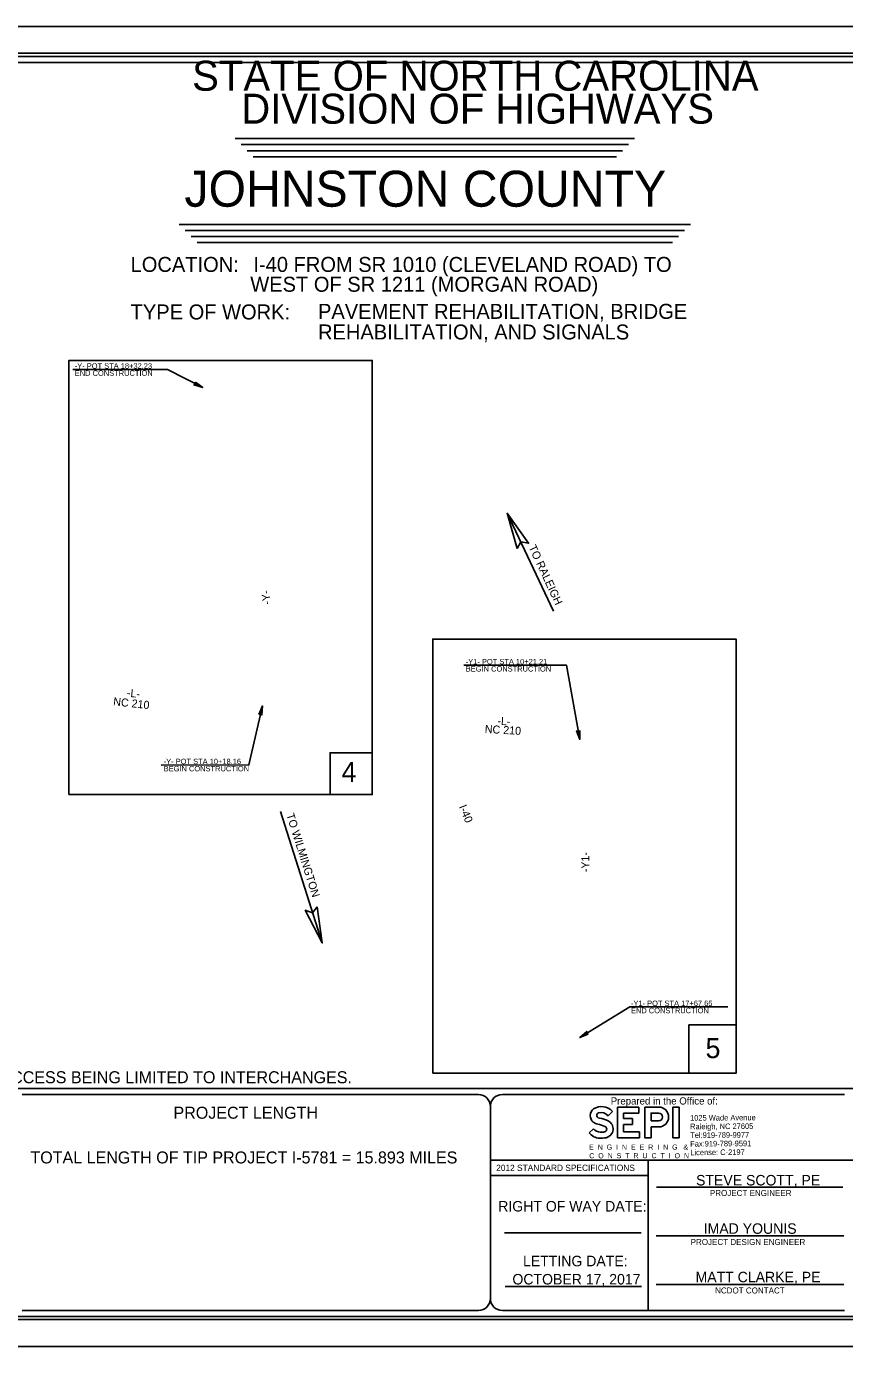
# Model space of a CAD drawing. Extents: x 2128934 to 2134034, y 641595 to 644895.
# Drawn here: x 2130661 to 2132705, y 641595 to 644895 of the extents above; entities that cross this region are included whole.
import ezdxf

# ---------------------------------------------------------------- set-up
doc = ezdxf.new("R2010")
doc.units = 0
for name, color, linetype in [('Old_Level_2', 7, 'Continuous'), ('Old_Level_61', 7, 'Continuous'), ('Prop Dimension Text', 7, 'Continuous'), ('Prop DSN Text', 7, 'Continuous'), ('Prop Terminator CELL', 7, 'Continuous'), ('Sheet Data Field CELL', 7, 'Continuous'), ('Sheet Plot Border Inside CELL', 7, 'Continuous'), ('Sheet Plot Border Outside CELL', 7, 'Continuous'), ('Sheet Title CELL', 7, 'Continuous'), ('Sheet Title Data Points CELL', 7, 'Continuous')]:
    doc.layers.add(name, color=color, linetype=linetype)

msp = doc.modelspace()

# ---------------------------------------------------------------- linework, layer by layer
at = {"layer": 'Old_Level_61'}
for p, q in [((2132124.8, 642183), (2132113.8, 642172.2)), ((2132137.3, 642117.1), (2132137.3, 642193.7)), ((2132137.3, 642193.7), (2132190.5, 642193.7)), ((2132190.5, 642193.7), (2132190.5, 642178.8)), ((2132240.3, 642193.8), (2132205.6, 642193.7)), ((2132276, 642193.8), (2132291.3, 642193.8)), ((2132276, 642117.1), (2132276, 642193.8)), ((2132291.3, 642193.8), (2132291.3, 642117.1)), ((2132190.5, 642178.8), (2132152.6, 642178.8)), ((2132152.6, 642178.8), (2132152.6, 642165.5)), ((2132152.6, 642165.5), (2132174.5, 642165.5)), ((2132174.5, 642150.6), (2132152.6, 642150.6)), ((2132152.6, 642150.6), (2132152.6, 642132)), ((2132174.5, 642165.5), (2132174.5, 642150.6)), ((2132240.3, 642159.1), (2132221.3, 642159.1)), ((2132066.5, 642129.7), (2132077.6, 642139.6)), ((2132192.3, 642117.1), (2132137.3, 642117.1)), ((2132152.6, 642132), (2132192.3, 642132)), ((2132192.3, 642132), (2132192.3, 642117.1)), ((2132291.3, 642117.1), (2132276, 642117.1))]:
    msp.add_line(p, q, dxfattribs=at)
for points in [[(2132205.6, 642193.7), (2132240.3, 642193.8)], [(2132240.3, 642144.2), (2132221.3, 642144.2), (2132221.3, 642117.1), (2132205.6, 642117.1), (2132205.6, 642193.7)], [(2132205.6, 642193.7), (2132205.6, 642117.1), (2132221.3, 642117.1), (2132221.3, 642144.2), (2132240.3, 642144.2)], [(2132221.3, 642159.1), (2132221.3, 642178.9), (2132240.3, 642178.9)], [(2132221.3, 642159.1), (2132221.3, 642178.9), (2132240.3, 642178.9)], [(2132240.3, 642159.1), (2132221.3, 642159.1)]]:
    msp.add_lwpolyline(points, dxfattribs=at)
for centre, radius, start, end in [((2132090.7, 642172.3), 21.3, 127.7369, 229.6652), ((2132097.6, 642158.3), 36.7, 42.1326, 122.978), ((2132096.3, 642156.7), 23.4, 41.6205, 105.1977), ((2132240.3, 642169), 24.8, 270.0084, 90.0084), ((2132240.3, 642169), 24.8, 270.0084, 90.0084), ((2132095.2, 642181.3), 31.1, 234.0274, 257.3507), ((2132091.7, 642173.1), 6.34, 103.5309, 215.5146), ((2132095.1, 642177.9), 12.1, 224.8335, 256.8487), ((2132070.5, 642058.6), 94, 67.7855, 79.0603), ((2132072.8, 642061.8), 106.2, 67.2046, 79.386), ((2132103.9, 642139.3), 22.7, 283.8986, 63.5915), ((2132240.3, 642169), 9.87, 270.0084, 90.0084), ((2132240.3, 642169), 9.87, 270.0084, 90.0084), ((2132093.5, 642149.6), 33.5, 216.3694, 269.0231), ((2132096.1, 642154.7), 23.8, 219.2142, 265.7728), ((2132097.2, 642166.6), 50.7, 265.1338, 283.7744), ((2132097.5, 642160.4), 29.6, 263.8471, 285.0484), ((2132103.1, 642138.9), 7.37, 286.1133, 66.6482)]:
    msp.add_arc(centre, radius, start, end, dxfattribs=at)
at = {"layer": 'Prop Dimension Text'}
for p, q in [((2130776.9, 644037.7), (2131013.2, 644037.8)), ((2131013.2, 644037.8), (2131101.3, 643992.3))]:
    msp.add_line(p, q, dxfattribs=at)
for points in [[(2131753.5, 643298.2), (2132009.9, 643298.5), (2132043.2, 643112.7)], [(2130996.9, 643048.8), (2131216.6, 643048.9), (2131250.2, 643196.6)], [(2132043.2, 642367.5), (2132167.9, 642444.1), (2132412.8, 642444.1)]]:
    msp.add_lwpolyline(points, dxfattribs=at)
at = {"layer": 'Prop DSN Text'}
for p, q in [((2131977.4, 643433.6), (2131862, 643678.1)), ((2131295.6, 642933), (2131399.6, 642604.2))]:
    msp.add_line(p, q, dxfattribs=at)
for points in [[(2130767, 642975), (2130767, 644060.1), (2131524.6, 644060.1), (2131524.6, 642975)], [(2131886.4, 643590.1), (2131862, 643678.1), (2131915.1, 643603.1), (2131895.7, 643606.7)], [(2131675.9, 642278.4), (2131675.9, 643363.5), (2132433.5, 643363.5), (2132433.5, 642278.4)], [(2131524.6, 642975), (2131419.2, 642975), (2131419.2, 643079.5), (2131524.6, 643079.5)], [(2131387.3, 642694.7), (2131399.6, 642604.2), (2131357.1, 642685.7), (2131375.8, 642679.5)], [(2132433.5, 642278.4), (2132315.9, 642278.4), (2132315.9, 642399.3), (2132433.5, 642399.3)]]:
    msp.add_lwpolyline(points, close=True, dxfattribs=at)
at = {"layer": 'Prop Terminator CELL'}
for points in [[(2131083.1, 644006), (2131101.3, 643992.3), (2131079.3, 643999.1), (2131083.7, 644001.3)], [(2131241.4, 643175.5), (2131250.2, 643196.6), (2131249, 643173.7), (2131245.8, 643177.4)], [(2132043, 643135.5), (2132043.2, 643112.7), (2132035.2, 643134.2), (2132039.7, 643132.1)], [(2132064.4, 642376), (2132043.2, 642367.5), (2132060.4, 642382.8), (2132060, 642377.8)]]:
    msp.add_lwpolyline(points, close=True, dxfattribs=at)
at = {"layer": 'Sheet Plot Border Inside CELL'}
msp.add_lwpolyline([(2128972.8, 641662.5), (2133972.3, 641662.5), (2133972.3, 644827.8), (2128972.8, 644827.8)], close=True, dxfattribs=at)
at = {"layer": 'Sheet Plot Border Outside CELL'}
msp.add_lwpolyline([(2128933.8, 641595.1), (2134033.8, 641595.1), (2134033.8, 644895.1), (2128933.8, 644895.1)], close=True, dxfattribs=at)
at = {"layer": 'Sheet Title CELL'}
for p, q in [((2131182, 644614.5), (2132180.2, 644614.5)), ((2131197, 644599.5), (2132165.2, 644599.5)), ((2131212, 644584.5), (2132150.2, 644584.5)), ((2131227, 644569.5), (2132135.2, 644569.5)), ((2131042, 644399.7), (2132320, 644399.7)), ((2131057, 644384.7), (2132305, 644384.7)), ((2131072, 644369.7), (2132290, 644369.7)), ((2131087, 644354.7), (2132275, 644354.7)), ((2129629.8, 642240.2), (2133889.8, 642240.2)), ((2130649.8, 642225.1), (2131789.8, 642225.1)), ((2131849.8, 642225.2), (2132704.8, 642225.2)), ((2131819.8, 642195.2), (2131819.8, 641715.2)), ((2132734.8, 642060.9), (2131819.8, 642060.9)), ((2132214.4, 642060.9), (2132214.4, 641685.2)), ((2132214.4, 642022.6), (2131819.8, 642022.7)), ((2132100.7, 642022.7), (2132100.7, 642022.7)), ((2132235.1, 641994), (2132700.6, 641994)), ((2132196.4, 641879.1), (2131855.2, 641879.1)), ((2132025.7, 641879.1), (2132025.7, 641879.1)), ((2132234.1, 641871.7), (2132702.8, 641871.7)), ((2132197.6, 641745.3), (2131856.4, 641745.3)), ((2132234.1, 641750.6), (2132702.8, 641750.6))]:
    msp.add_line(p, q, dxfattribs=at)
for points in [[(2133904.8, 644820.1), (2129464.7, 644820.2)], [(2133889.8, 644805.1), (2129629.8, 644805.1)], [(2130649.8, 641685.1), (2131789.8, 641685.1)], [(2131849.8, 641685.2), (2132704.8, 641685.1)], [(2129464.8, 641670.1), (2133904.8, 641670.1)]]:
    msp.add_lwpolyline(points, dxfattribs=at)
for centre, start, end in [((2131789.8, 642195.3), 0, 90), ((2131849.8, 642195.3), 90, 180), ((2131789.8, 641715.3), 270, 360), ((2131849.8, 641715.3), 180, 270)]:
    msp.add_arc(centre, 30, start, end, dxfattribs=at)
at = {"layer": 'Sheet Title Data Points CELL'}
for p, q in [((2131685.7, 644444.4), (2131685.7, 644444.4)), ((2132045.8, 644281.3), (2132045.8, 644281.3))]:
    msp.add_line(p, q, dxfattribs=at)

# ---------------------------------------------------------------- texts
at = {"layer": 'Old_Level_2'}
for s, height, rotation, p in [('1025 Wade Avenue', 13.973, 0.3479, (2132318.7, 642159.8)), ('Raleigh, NC 27605', 13.973, 0.3479, (2132318.9, 642138.2)), ('Tel:919-789-9977 ', 13.973, 0.3479, (2132319, 642116.6)), ('E  N  G  I  N  E  E  R  I  N  G   &', 12.75, 0.0085, (2132066.4, 642087.4)), ('Fax:919-789-9591', 13.973, 0.3479, (2132319.1, 642095.1)), ('License: C-2197', 13.973, 0.3479, (2132319.3, 642073.5)), ('C  O  N  S  T  R  U  C  T  I  O  N', 12.75, 0.0085, (2132066.8, 642065.9))]:
    msp.add_text(s, height=height, rotation=rotation, dxfattribs=at).set_placement(p)
at = {"layer": 'Prop Dimension Text'}
for s, p in [('-Y- POT STA 18+32.23', (2130781.4, 644039.6)), ('END CONSTRUCTION', (2130781.5, 644021.6)), ('-Y1- POT STA 10+21.21', (2131758.4, 643300.5)), ('BEGIN CONSTRUCTION', (2131758.4, 643282.5)), ('-Y- POT STA 10+18.16', (2131003.6, 643051)), ('BEGIN CONSTRUCTION', (2131003.6, 643033)), ('-Y1- POT STA 17+67.65', (2132171.1, 642446.4)), ('END CONSTRUCTION', (2132171.1, 642428.4))]:
    msp.add_text(s, height=13.5, rotation=0.0155, dxfattribs=at).set_placement(p)
at = {"layer": 'Prop DSN Text'}
for s, rotation, p in [('TO RALEIGH', 294.9563, (2131914.7, 643593.4)), ('-Y-', 95.3672, (2131270.7, 643450.7)), ('-L-', 353.8891, (2130910.9, 643219.9)), ('NC 210', 353.8891, (2130876.8, 643198.2)), ('NC 210', 356.749, (2131805.4, 643129.2)), ('-L-', 356.749, (2131837, 643149.5)), ('I-40', 292.3368, (2131740.9, 642944.8)), ('TO WILMINGTON', 287.4843, (2131309.7, 642924.6)), ('-Y1-', 89.836, (2132066.8, 642780.8))]:
    msp.add_text(s, height=20, rotation=rotation, dxfattribs=at).set_placement(p)
for s, height, p in [('4', 50, (2131448.1, 643006.8)), ('5', 50, (2132357.4, 642316.2)), ('THIS IS A CONTROLLED-ACCESS PROJECT WITH ACCESS BEING LIMITED TO INTERCHANGES.', 30, (2129630.5, 642253.4)), ('TOTAL LENGTH OF TIP PROJECT I-5781 = 15.893 MILES', 30, (2130670.6, 642052.9))]:
    msp.add_text(s, height=height, dxfattribs=at).set_placement(p)
at = {"layer": 'Sheet Data Field CELL'}
for s, height, p in [('JOHNSTON COUNTY', 90, (2131055.5, 644444.4)), ('I-40 FROM SR 1010 (CLEVELAND ROAD) TO ', 37.5, (2131227.8, 644281.4)), ('PAVEMENT REHABILITATION, BRIDGE ', 37.5, (2131389.2, 644164.1)), ('REHABILITATION, AND SIGNALS', 37.5, (2131389.2, 644112.5)), ('OCTOBER 17, 2017', 26.25, (2131874.9, 641750.4)), ('MATT CLARKE, PE', 26.25, (2132332.4, 641755.9))]:
    msp.add_text(s, height=height, dxfattribs=at).set_placement(p)
for s, height, p in [('WEST OF SR 1211 (MORGAN ROAD)', 37.5, (2131220, 644231.8)), ('STEVE SCOTT, PE', 26.25, (2132333.7, 641997.9)), ('IMAD YOUNIS', 26.25, (2132352.8, 641877))]:
    msp.add_text(s, height=height, rotation=360, dxfattribs=at).set_placement(p)
at = {"layer": 'Sheet Title CELL'}
for s, height, p in [('STATE OF NORTH CAROLINA', 75, (2131074.6, 644734.3)), ('DIVISION OF HIGHWAYS', 75, (2131197.3, 644651.9)), ('LOCATION: ', 37.5, (2130921, 644281.4)), ('TYPE OF WORK:', 37.5, (2130921, 644162.6)), ('Prepared in the Office of:', 17.998, (2132120.5, 642200.2)), ('PROJECT LENGTH', 29.999, (2131028.1, 642164.7)), ('2012 STANDARD SPECIFICATIONS', 15.6, (2131834.3, 642034.2)), ('PROJECT ENGINEER', 14.998, (2132368.2, 641971.5)), ('RIGHT OF WAY DATE: ', 26.249, (2131839.4, 641932.8)), ('PROJECT DESIGN ENGINEER', 14.998, (2132320.2, 641849.1)), ('LETTING DATE:', 26.249, (2131901.4, 641795.9))]:
    msp.add_text(s, height=height, rotation=360, dxfattribs=at).set_placement(p)
msp.add_text('NCDOT CONTACT', height=14.998, dxfattribs=at).set_placement((2132381.3, 641727.9))

doc.saveas('drawing.dxf')
